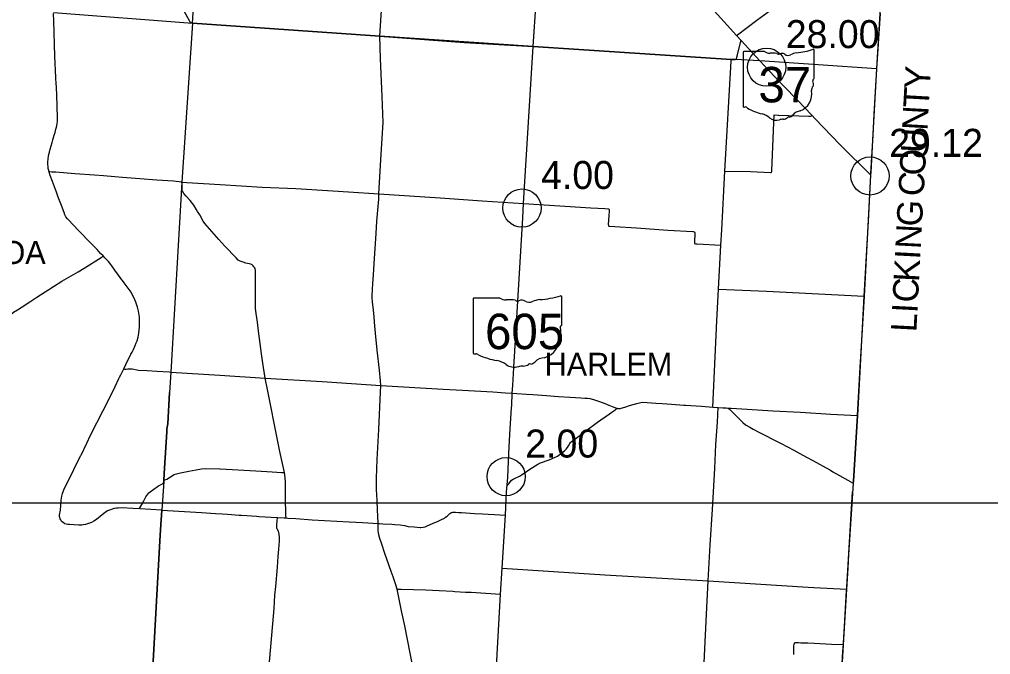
# Model space of a CAD drawing. Extents: x 1729596 to 1934326, y 644115 to 911751.
# Drawn here: x 1863218 to 1901343, y 778712 to 803658 of the extents above; entities that cross this region are included whole.
import ezdxf

# ---------------------------------------------------------------- set-up
doc = ezdxf.new("R2010")
doc.units = 0
for name, color, linetype in [('Default', 7, 'Continuous'), ('GM_X_Adjacent_County', 7, 'Continuous'), ('GM_X_Adjacent_County_Text', 7, 'Continuous'), ('GM_X_County', 7, 'Continuous'), ('GM_X_County_Road', 7, 'Continuous'), ('GM_X_State_Route', 7, 'Continuous'), ('GM_X_State_Shield', 7, 'Continuous'), ('GM_X_Township', 7, 'Continuous'), ('GM_X_Township_Road', 7, 'Continuous'), ('GM_X_Township_Text', 7, 'Continuous'), ('SC_Scratch1', 7, 'Continuous')]:
    doc.layers.add(name, color=color, linetype=linetype)

msp = doc.modelspace()

# ---------------------------------------------------------------- linework, layer by layer
at = {"layer": 'Default'}
for centre in [(1892552, 801780), (1896611, 797510), (1882946, 796248), (1882325, 785700)]:
    msp.add_circle(centre, 750, dxfattribs=at)
at = {"layer": 'GM_X_Adjacent_County'}
msp.add_line((1895282, 774451), (1895925, 785099), dxfattribs=at)
at = {"layer": 'GM_X_County'}
msp.add_lwpolyline([(1897004, 803896), (1896867, 801714), (1896762, 799856), (1896723, 799168), (1896641, 797645), (1896629, 797539), (1896376, 792790), (1896278, 791042), (1896113, 788102), (1895956, 785523), (1895947, 785445), (1895896, 784633), (1895772, 782650), (1895741, 782103), (1895686, 781278), (1895557, 779101), (1895391, 776219)], dxfattribs=at)
at = {"layer": 'GM_X_County_Road'}
for points in [[(1896877, 801685), (1896878, 801713), (1896961, 803039), (1897015, 803890), (1897038, 804349), (1897401, 810812), (1897452, 811576), (1897482, 811930), (1897540, 812982), (1897564, 813416)], [(1867396, 808359), (1867578, 807822), (1867722, 807411), (1867905, 806886), (1867988, 806661), (1868047, 806496), (1868091, 806398), (1868141, 806295), (1868218, 806162), (1868595, 805529), (1868820, 805149), (1868910, 805003), (1868961, 804924), (1869020, 804860), (1869146, 804736), (1869355, 804533), (1869481, 804376), (1869529, 804297), (1869678, 803996), (1869885, 803620), (1869914, 803562), (1869930, 803545)], [(1877369, 802994), (1877508, 805242), (1877600, 806419), (1877627, 806773)], [(1864668, 796879), (1864590, 797083), (1864513, 797287), (1864422, 797530), (1864380, 797664), (1864367, 797719), (1864351, 797802), (1864341, 797885), (1864336, 797962), (1864335, 798045), (1864343, 798179), (1864359, 798293), (1864372, 798348), (1864397, 798443), (1864431, 798566), (1864503, 798820), (1864532, 798925), (1864588, 799118), (1864615, 799218), (1864650, 799343), (1864671, 799432), (1864694, 799556), (1864707, 799664), (1864713, 799761), (1864693, 800283), (1864667, 801023), (1864657, 801114), (1864648, 801383), (1864604, 802208), (1864568, 803602), (1864561, 803891)], [(1869930, 803545), (1869936, 803538), (1870008, 803514), (1877369, 802994)], [(1877332, 796811), (1877420, 798367), (1877499, 799608), (1877454, 800633), (1877398, 802125), (1877369, 802994)], [(1896641, 797536), (1896646, 797601), (1896729, 799110), (1896778, 799931), (1896816, 800595), (1896842, 801059), (1896877, 801685)], [(1869596, 797271), (1869264, 797299), (1868606, 797350), (1867949, 797398), (1867262, 797449), (1866957, 797476), (1866512, 797510), (1866160, 797537), (1865389, 797594), (1864651, 797652), (1864490, 797665), (1864412, 797670), (1864397, 797669), (1864380, 797664)], [(1872512, 792112), (1872490, 792299), (1872490, 792441), (1872490, 792557), (1872490, 792879), (1872488, 793281), (1872492, 793732), (1872489, 793791), (1872473, 793859), (1872454, 793904), (1872424, 793943), (1872389, 793984), (1872352, 794016), (1872303, 794045), (1872239, 794060), (1872103, 794090), (1871997, 794120), (1871888, 794161), (1871806, 794204), (1871722, 794290), (1871282, 794757), (1871051, 795010), (1870503, 795638), (1870435, 795737), (1870300, 795980), (1870212, 796114), (1870156, 796211), (1870067, 796366), (1869918, 796549), (1869770, 796721), (1869677, 796824), (1869643, 796870), (1869617, 796918), (1869609, 796940), (1869604, 796966), (1869603, 796991), (1869604, 797040), (1869606, 797200), (1869596, 797271)], [(1869596, 797271), (1869794, 797255), (1871103, 797168), (1872753, 797073), (1874071, 797014), (1875527, 796924), (1876143, 796885), (1877332, 796811)], [(1896288, 791046), (1896384, 792784), (1896550, 795738), (1896641, 797536)], [(1866503, 794368), (1866405, 794466), (1866272, 794620), (1866088, 794799), (1865870, 795027), (1865711, 795195), (1865579, 795328), (1865290, 795631), (1865178, 795747), (1865101, 795824), (1865042, 795902), (1865004, 795980), (1864969, 796070), (1864868, 796347), (1864745, 796675), (1864687, 796830), (1864668, 796879)], [(1877401, 789284), (1877390, 789464), (1877348, 789877), (1877267, 790662), (1877198, 791335), (1877163, 791768), (1877144, 791994), (1877118, 792235), (1877082, 792567), (1877064, 792727), (1877062, 792815), (1877091, 793291), (1877116, 793631), (1877141, 794076), (1877219, 795256), (1877251, 795728), (1877331, 796597), (1877332, 796811)], [(1877332, 796811), (1879735, 796644), (1881379, 796538), (1883003, 796429), (1885646, 796260), (1886199, 796226), (1886342, 796212), (1886365, 796195), (1886376, 796165), (1886375, 796124), (1886362, 795947), (1886335, 795601), (1886339, 795571), (1886347, 795554), (1886359, 795544), (1886386, 795534), (1886593, 795523), (1887442, 795472), (1888679, 795387), (1889657, 795329), (1889685, 795326), (1889702, 795320), (1889718, 795310), (1889731, 795291), (1889734, 795271), (1889715, 794891), (1889718, 794875), (1889726, 794861), (1889758, 794850), (1889831, 794843), (1890758, 794790)], [(1862331, 790993), (1862331, 790993), (1862425, 791233), (1862464, 791347), (1862553, 791556), (1862621, 791712), (1862718, 791870), (1862878, 792073), (1862988, 792163), (1863137, 792257), (1863326, 792369), (1863622, 792566), (1863901, 792746), (1864887, 793380), (1865528, 793748), (1865763, 793892), (1866421, 794305), (1866453, 794326), (1866503, 794368)], [(1867241, 793436), (1867175, 793524), (1867110, 793619), (1866968, 793805), (1866845, 793974), (1866805, 794027), (1866710, 794146), (1866624, 794245), (1866569, 794300), (1866503, 794368)], [(1867153, 789604), (1867200, 789700), (1867319, 789935), (1867396, 790101), (1867504, 790327), (1867565, 790450), (1867596, 790512), (1867641, 790592), (1867690, 790690), (1867763, 790847), (1867804, 790955), (1867838, 791037), (1867877, 791180), (1867910, 791333), (1867929, 791569), (1867933, 791826), (1867927, 791967), (1867917, 792047), (1867886, 792196), (1867849, 792363), (1867813, 792478), (1867788, 792552), (1867745, 792648), (1867704, 792736), (1867647, 792848), (1867599, 792941), (1867524, 793055), (1867442, 793157), (1867330, 793312), (1867263, 793407), (1867241, 793436)], [(1872978, 777819), (1873212, 780520), (1873251, 781046), (1873282, 781384), (1873344, 782141), (1873381, 782566), (1873402, 782850), (1873426, 783163), (1873427, 783321), (1873418, 783441), (1873405, 783505), (1873393, 783554), (1873368, 783600), (1873335, 783652), (1873325, 783665), (1873319, 783693), (1873320, 783725), (1873324, 783797), (1873340, 783963), (1873351, 784093), (1873606, 784082), (1873683, 784083), (1873682, 784168), (1873669, 784889), (1873663, 785162), (1873657, 785466), (1873655, 785664), (1873627, 785869), (1873446, 786682), (1873351, 787142), (1872964, 789059), (1872863, 789571), (1872778, 790159), (1872727, 790526), (1872666, 790930), (1872604, 791411), (1872559, 791766), (1872513, 792107), (1872512, 792112)], [(1895958, 785443), (1895961, 785520), (1896121, 788099), (1896226, 789994), (1896288, 791046)], [(1865634, 786531), (1865642, 786548), (1865861, 787020), (1866012, 787331), (1866508, 788298), (1866790, 788861), (1866977, 789237), (1867126, 789549), (1867153, 789604)], [(1872863, 789571), (1875101, 789435), (1877401, 789284), (1879855, 789132), (1880616, 789098), (1881806, 789028), (1882295, 788997), (1882567, 788975)], [(1878692, 778117), (1878562, 778774), (1878349, 779845), (1878222, 780426), (1878129, 780890), (1878049, 781278), (1877993, 781449), (1877886, 781763), (1877812, 781976), (1877647, 782454), (1877568, 782686), (1877444, 783047), (1877370, 783269), (1877325, 783417), (1877310, 783511), (1877305, 783560), (1877299, 783658), (1877295, 783854), (1877283, 784157), (1877278, 784375), (1877260, 784771), (1877240, 785195), (1877237, 785645), (1877265, 786378), (1877326, 787557), (1877396, 789022), (1877401, 789284)], [(1882567, 788975), (1882741, 788963), (1883125, 788937), (1883370, 788921), (1883909, 788888), (1884378, 788846), (1884839, 788818), (1885253, 788795), (1885410, 788787), (1885513, 788777), (1885610, 788763), (1885755, 788729), (1885907, 788682), (1886172, 788583), (1886362, 788508), (1886482, 788459), (1886595, 788414), (1886653, 788392), (1886680, 788385), (1886713, 788376), (1886731, 788374), (1886750, 788372), (1886768, 788373), (1886797, 788377), (1887028, 788442), (1887172, 788488), (1887461, 788573), (1887615, 788617), (1887686, 788622), (1887858, 788617), (1888201, 788587), (1888444, 788572), (1888821, 788548), (1889303, 788508), (1889365, 788503), (1889989, 788465), (1890439, 788430), (1890646, 788418), (1890829, 788409), (1890966, 788400), (1891025, 788386), (1891044, 788379), (1891062, 788369), (1891080, 788359), (1891096, 788347), (1891113, 788333), (1891216, 788229), (1891350, 788086), (1891449, 787991), (1891616, 787833), (1891727, 787741), (1891886, 787645), (1892027, 787567), (1892268, 787440), (1892505, 787318), (1892785, 787171), (1893118, 786998), (1893620, 786737), (1893978, 786545), (1894504, 786258), (1894890, 786043), (1895054, 785951), (1895157, 785895), (1895411, 785750), (1895736, 785562), (1895925, 785459), (1895958, 785443)], [(1868439, 777975), (1868734, 783178), (1868751, 783613), (1868806, 784389), (1867942, 784436), (1867676, 784450), (1867236, 784472), (1867100, 784466), (1867030, 784459), (1866941, 784445), (1866864, 784426), (1866789, 784401), (1866682, 784352), (1866580, 784287), (1866468, 784200), (1866242, 784020), (1866138, 783951), (1866042, 783902), (1865893, 783841), (1865807, 783819), (1865720, 783803), (1865668, 783796), (1865550, 783792), (1865186, 783818), (1865114, 783826), (1865049, 783836), (1865006, 783850), (1864986, 783859), (1864948, 783880), (1864897, 783921), (1864860, 783965), (1864838, 784001), (1864822, 784040), (1864798, 784100), (1864795, 784137), (1864796, 784206), (1864829, 784383), (1864841, 784568), (1864856, 784770), (1864885, 784933), (1864914, 785038), (1864961, 785176), (1865080, 785426), (1865258, 785787), (1865446, 786179), (1865634, 786531)], [(1895289, 774451), (1895396, 776220), (1895437, 776878), (1895549, 778840), (1895565, 779105), (1895662, 780753), (1895692, 781225), (1895695, 781277), (1895727, 781798), (1895781, 782638), (1895891, 784421), (1895958, 785443)], [(1868806, 784389), (1870363, 784286), (1870916, 784253), (1871172, 784239), (1871392, 784221), (1871840, 784193), (1871932, 784185), (1872143, 784168), (1872331, 784155), (1872524, 784144), (1872620, 784137), (1873351, 784093)]]:
    msp.add_lwpolyline(points, dxfattribs=at)
at = {"layer": 'GM_X_State_Route'}
for points in [[(1883945, 807913), (1884008, 807879), (1884894, 807348), (1887358, 805901), (1889702, 804583), (1889965, 804433), (1890068, 804367), (1890146, 804309), (1890221, 804252), (1890297, 804190), (1890369, 804123), (1890999, 803432), (1891373, 803023), (1891553, 802825), (1892288, 802025), (1892862, 801410), (1894115, 800116), (1894249, 799980), (1894338, 799884), (1894447, 799772), (1895444, 798735), (1896641, 797536)], [(1882720, 791504), (1882978, 795867), (1883003, 796429), (1883088, 797714), (1883392, 802588), (1883500, 804351), (1883543, 804938), (1883588, 805754), (1883679, 807097), (1883681, 807137)], [(1882488, 787572), (1882536, 788409), (1882544, 788490), (1882567, 788975), (1882584, 789282), (1882631, 789981), (1882641, 790234), (1882655, 790407), (1882720, 791504)], [(1881788, 775208), (1881798, 775531), (1881825, 775865), (1881869, 776825), (1881921, 777694), (1881972, 778710), (1882105, 781091), (1882171, 782101), (1882295, 784185), (1882344, 785085), (1882365, 785373), (1882388, 785663), (1882412, 786305), (1882436, 786610), (1882462, 787116), (1882488, 787572)]]:
    msp.add_lwpolyline(points, dxfattribs=at)
at = {"layer": 'GM_X_State_Shield'}
for p, q in [((1891630, 802365), (1891630, 800251)), ((1891630, 802365), (1891630, 800251)), ((1892472, 802401), (1891657, 802401)), ((1892472, 802401), (1891657, 802401)), ((1894414, 801348), (1894414, 802453)), ((1894414, 801348), (1894414, 802453)), ((1894414, 801348), (1894414, 801348)), ((1894414, 801348), (1894414, 801348)), ((1881028, 792671), (1881028, 790558)), ((1881028, 792671), (1881028, 790558)), ((1882082, 792708), (1881063, 792708)), ((1882082, 792708), (1881063, 792708)), ((1884509, 791655), (1884509, 792760)), ((1884509, 791655), (1884509, 792760)), ((1884508, 791655), (1884509, 791655)), ((1884508, 791655), (1884509, 791655))]:
    msp.add_line(p, q, dxfattribs=at)
for centre, radius, start, end in [((1891661, 802369), 32.3, 98.1301, 188.1301), ((1891661, 802369), 32.3, 98.1301, 188.1301), ((1892667, 802646), 313, 231.6195, 271.1119), ((1892667, 802646), 313, 231.6195, 271.1119), ((1892770, 801215), 1123, 80.4867, 94.9883), ((1892770, 801215), 1123, 80.4867, 94.9883), ((1893025, 802380), 90.3, 219.7921, 297.1024), ((1893025, 802380), 90.3, 219.7921, 297.1024), ((1893158, 802136), 188, 54.4667, 119.1411), ((1893158, 802136), 188, 54.4667, 119.1411), ((1893400, 802471), 226, 233.8562, 294.8282), ((1893400, 802471), 226, 233.8562, 294.8282), ((1893799, 801756), 594, 97.3462, 120.7689), ((1893799, 801756), 594, 97.3462, 120.7689), ((1893422, 805282), 2953, 275.8445, 288.9065), ((1893422, 805282), 2953, 275.8445, 288.9065), ((1894383, 802458), 31, 351.8621, 97.738), ((1894383, 802458), 31, 351.8621, 97.738), ((1894525, 800885), 210, 136.8065, 186.9296), ((1894525, 800885), 210, 136.8065, 186.9296), ((1894407, 801267), 48, 107.944, 210.337), ((1894407, 801267), 48, 107.944, 210.337), ((1894102, 801127), 288, 340.033, 23.6496), ((1894102, 801127), 288, 340.033, 23.6496), ((1894381, 801344), 33.2, 289.6038, 7.7341), ((1894381, 801344), 33.2, 289.6038, 7.7341), ((1893587, 800745), 739, 292.3089, 8.9858), ((1893587, 800745), 739, 292.3089, 8.9858), ((1891662, 800247), 32.5, 171.9584, 258.3066), ((1891662, 800247), 32.5, 171.9584, 258.3066), ((1891667, 800463), 248, 267.339, 280.6039), ((1891667, 800463), 248, 267.339, 280.6039), ((1891717, 800129), 89.5, 29.7484, 93.2717), ((1891717, 800129), 89.5, 29.7484, 93.2717), ((1892848, 802028), 2132, 240.4129, 257.1985), ((1892848, 802028), 2132, 240.4129, 257.1985), ((1892212, 799302), 667, 47.1842, 75.836), ((1892212, 799302), 667, 47.1842, 75.836), ((1893386, 800047), 239, 282.8732, 323.2771), ((1893386, 800047), 239, 282.8732, 323.2771), ((1893899, 799658), 404, 94.4031, 142.5768), ((1893899, 799658), 404, 94.4031, 142.5768), ((1892934, 800119), 423, 230.7004, 286.2918), ((1892934, 800119), 423, 230.7004, 286.2918), ((1893178, 799388), 348, 85.6951, 111.2099), ((1893178, 799388), 348, 85.6951, 111.2099), ((1893209, 799961), 226, 268.777, 315.5493), ((1893209, 799961), 226, 268.777, 315.5493), ((1893413, 799756), 63.5, 65.7517, 132.6484), ((1893413, 799756), 63.5, 65.7517, 132.6484)]:
    msp.add_arc(centre, radius, start, end, dxfattribs=at)
for centre, major_axis, start_param, end_param in [((1881068, 792676), (40.3, 0), 1.712693, 3.28349), ((1881068, 792676), (40.3, 0), 1.712693, 3.28349), ((1882325, 792953), (391, 0), 4.042523, 4.731795), ((1882325, 792953), (391, 0), 4.042523, 4.731795), ((1882454, 791521), (1404, 0), 1.404758, 1.657858), ((1882454, 791521), (1404, 0), 1.404758, 1.657858), ((1882773, 792687), (113, 0), 3.836095, 5.185415), ((1882773, 792687), (113, 0), 3.836095, 5.185415), ((1882939, 792443), (235, 0), 0.950623, 2.079405), ((1882939, 792443), (235, 0), 0.950623, 2.079405), ((1883740, 792062), (743, 0), 1.699011, 2.107814), ((1883740, 792062), (743, 0), 1.699011, 2.107814), ((1883269, 795589), (3691, 0), 4.814394, 5.042369), ((1883269, 795589), (3691, 0), 4.814394, 5.042369), ((1884470, 792765), (38.7, 0), 6.141152, 7.989035), ((1884470, 792765), (38.7, 0), 6.141152, 7.989035), ((1883241, 792778), (282, 0), 4.081561, 5.145723), ((1883241, 792778), (282, 0), 4.081561, 5.145723), ((1884500, 791574), (60, 0), 1.883978, 3.671073), ((1884500, 791574), (60, 0), 1.883978, 3.671073), ((1884118, 791434), (360, 0), 5.934695, 6.695948), ((1884118, 791434), (360, 0), 5.934695, 6.695948), ((1884468, 791650), (41.5, 0), 5.05454, 6.418171), ((1884468, 791650), (41.5, 0), 5.05454, 6.418171), ((1883476, 791051), (923, 0), 5.101752, 6.440018), ((1883476, 791051), (923, 0), 5.101752, 6.440018), ((1884648, 791192), (262, 0), 2.387724, 3.262537), ((1884648, 791192), (262, 0), 2.387724, 3.262537), ((1881069, 790554), (40.7, 0), 3.00124, 4.508301), ((1881069, 790554), (40.7, 0), 3.00124, 4.508301), ((1881075, 790770), (310, 0), 4.665946, 4.897461), ((1881075, 790770), (310, 0), 4.665946, 4.897461), ((1881138, 790436), (112, 0), 0.519207, 1.627899), ((1881138, 790436), (112, 0), 0.519207, 1.627899), ((1882552, 792335), (2665, 0), 4.195997, 4.488961), ((1882552, 792335), (2665, 0), 4.195997, 4.488961), ((1883865, 789965), (506, 0), 1.647645, 2.488434), ((1883865, 789965), (506, 0), 1.647645, 2.488434), ((1881757, 789609), (834, 0), 0.823519, 1.323587), ((1881757, 789609), (834, 0), 0.823519, 1.323587), ((1882659, 790426), (529, 0), 4.026481, 4.996735), ((1882659, 790426), (529, 0), 4.026481, 4.996735), ((1882965, 789695), (435, 0), 1.495662, 1.94098), ((1882965, 789695), (435, 0), 1.495662, 1.94098), ((1883003, 790268), (282, 0), 4.691044, 5.507374), ((1883003, 790268), (282, 0), 4.691044, 5.507374), ((1883258, 790063), (79.4, 0), 1.147584, 2.315152), ((1883258, 790063), (79.4, 0), 1.147584, 2.315152), ((1883224, 790353), (298, 0), 4.937069, 5.64225), ((1883224, 790353), (298, 0), 4.937069, 5.64225)]:
    msp.add_ellipse(centre, major_axis=major_axis, ratio=0.8, start_param=start_param, end_param=end_param, dxfattribs=at)
at = {"layer": 'GM_X_Township'}
for points in [[(1896867, 801714), (1892288, 802025), (1891297, 802083), (1891221, 802088), (1891165, 802089), (1883392, 802588), (1877369, 802994), (1870008, 803514), (1870309, 808163)], [(1864561, 803926), (1870008, 803514), (1869596, 797271), (1869163, 789806), (1869111, 789007), (1869039, 787768), (1869000, 787580), (1869008, 787459), (1868914, 786029), (1868892, 785569), (1868890, 785515), (1868806, 784389), (1868751, 783613), (1868734, 783178), (1868439, 777975), (1868321, 776001)]]:
    msp.add_lwpolyline(points, dxfattribs=at)
at = {"layer": 'GM_X_Township_Road'}
for points in [[(1891373, 803023), (1891387, 803039), (1891405, 803057), (1892171, 803626), (1892889, 804151), (1893142, 808538), (1893444, 812998), (1893450, 813114), (1893446, 813209)], [(1877369, 802994), (1880691, 802757), (1883392, 802588)], [(1883392, 802588), (1891165, 802089)], [(1891312, 802088), (1891337, 802094), (1891347, 802102), (1891354, 802110), (1891365, 802128), (1891402, 802264), (1891525, 802755), (1891537, 802794), (1891544, 802811), (1891553, 802825)], [(1890439, 788430), (1890599, 791825), (1890663, 793067), (1890758, 794790), (1890789, 795400), (1890905, 797697), (1891157, 802023), (1891165, 802089), (1891207, 802088)], [(1891207, 802088), (1891221, 802088), (1891297, 802083), (1891312, 802088)], [(1890905, 797697), (1891923, 797682), (1892705, 797649), (1892735, 797650), (1892749, 797657), (1892754, 797681), (1892755, 797718), (1892849, 799904), (1892999, 799898)], [(1892999, 799898), (1893021, 799897), (1894207, 799861), (1894280, 799859), (1894312, 799865), (1894338, 799884)], [(1890663, 793067), (1892550, 792979), (1896384, 792784)], [(1867319, 789935), (1867341, 789922), (1867365, 789918), (1867384, 789918), (1867408, 789922), (1867479, 789935), (1867531, 789940), (1867600, 789940), (1867638, 789937), (1867706, 789923), (1867821, 789895), (1867896, 789887), (1868229, 789864), (1868613, 789842), (1869090, 789811)], [(1869090, 789811), (1869163, 789806), (1871085, 789686), (1872863, 789571)], [(1868892, 785569), (1868914, 786029), (1869008, 787459), (1869000, 787580), (1869039, 787768), (1869111, 789007)], [(1882683, 785641), (1882855, 785721), (1882997, 785815), (1883257, 785993), (1883565, 786185), (1883679, 786242), (1884012, 786364), (1884230, 786446), (1884346, 786511), (1884516, 786635), (1884621, 786715), (1884686, 786778), (1884731, 786841), (1884769, 786909), (1884825, 787001), (1884855, 787037), (1884882, 787064), (1885068, 787213), (1885458, 787501), (1885907, 787835), (1886041, 787935), (1886384, 788169), (1886469, 788228), (1886553, 788290), (1886680, 788385)], [(1889887, 774731), (1890002, 776489), (1890176, 780026), (1890259, 781603), (1890338, 783022), (1890423, 784415), (1890516, 786023), (1890561, 786967), (1890617, 787839), (1890646, 788418)], [(1890966, 788400), (1891033, 788396), (1891153, 788392), (1891791, 788356), (1892800, 788289), (1893883, 788232), (1895073, 788154), (1896121, 788099)], [(1868902, 785570), (1868932, 785574), (1869001, 785603), (1869292, 785779), (1869311, 785786)], [(1869311, 785786), (1869335, 785796), (1869538, 785844), (1869873, 785912), (1870158, 785969), (1870363, 786009), (1870524, 786025), (1871080, 786004), (1871097, 786003)], [(1871097, 786003), (1872502, 785926), (1873145, 785890), (1873503, 785869), (1873627, 785869)], [(1867942, 784436), (1867949, 784478), (1868023, 784612), (1868101, 784749), (1868183, 784905), (1868256, 785017), (1868303, 785069), (1868353, 785099), (1868641, 785317), (1868679, 785339), (1868830, 785413), (1868860, 785439), (1868876, 785462), (1868890, 785515), (1868891, 785527)], [(1868891, 785527), (1868892, 785569), (1868902, 785570)], [(1882365, 785373), (1882398, 785385), (1882433, 785419), (1882534, 785556), (1882606, 785605), (1882683, 785641)], [(1878710, 783724), (1878718, 783723), (1878952, 783700), (1878974, 783698), (1879074, 783716), (1879141, 783735), (1879196, 783761), (1879454, 783879), (1879626, 783945), (1879759, 784003), (1879901, 784076), (1879948, 784106), (1880010, 784152), (1880078, 784216), (1880118, 784255), (1880153, 784278), (1880179, 784290), (1880195, 784296), (1880230, 784302), (1880247, 784303), (1880334, 784300), (1880449, 784295), (1880574, 784290), (1881079, 784258), (1881400, 784242), (1881619, 784230), (1881872, 784212), (1882079, 784200), (1882295, 784185)], [(1873683, 784083), (1873753, 784073), (1874065, 784055), (1874709, 784010), (1876165, 783928), (1876686, 783898), (1877295, 783854)], [(1877295, 783854), (1877356, 783857), (1877485, 783848), (1877833, 783829), (1877952, 783822), (1878166, 783809), (1878334, 783779), (1878476, 783745), (1878710, 783724)], [(1882171, 782101), (1886206, 781843), (1890259, 781603)], [(1890259, 781603), (1890259, 781603), (1894179, 781364)], [(1878049, 781278), (1878201, 781278), (1879179, 781250), (1879698, 781229), (1880226, 781199), (1880311, 781191), (1880734, 781168), (1880958, 781163), (1882105, 781091)], [(1894179, 781364), (1894411, 781350), (1895695, 781277)], [(1893617, 778714), (1893624, 779045), (1893632, 779127), (1893640, 779161), (1893657, 779180), (1893679, 779187), (1893716, 779191), (1893800, 779184), (1893892, 779175), (1894041, 779168), (1894167, 779168), (1894412, 779159), (1895102, 779119), (1895565, 779105)]]:
    msp.add_lwpolyline(points, dxfattribs=at)
at = {"layer": 'SC_Scratch1'}
msp.add_lwpolyline([(1730291, 784675), (1926541, 784675), (1926541, 650175), (1730291, 650175)], close=True, dxfattribs=at)

# ---------------------------------------------------------------- texts
at = {"layer": 'Default'}
for s, p in [('28.00', (1893302, 802530)), ('29.12', (1897361, 798260)), ('4.00', (1883696, 796998)), ('2.00', (1883075, 786450))]:
    msp.add_text(s, height=1100, dxfattribs=at).set_placement(p)
at = {"layer": 'GM_X_Adjacent_County_Text'}
for s, rotation, p in [('Y', 86.7665, (1898954, 800905)), ('T', 86.7674, (1898911, 800158)), ('N', 86.7675, (1898862, 799275)), ('U', 86.7602, (1898812, 798392)), ('O', 86.7321, (1898761, 797508)), ('C', 86.4487, (1898710, 796690)), ('G', 86.9419, (1898647, 795506)), ('N', 86.9747, (1898600, 794623)), ('K', 86.9789, (1898532, 793332)), ('I', 86.9739, (1898579, 794215)), ('C', 86.98, (1898489, 792519)), ('I', 86.9808, (1898468, 792110)), ('L', 86.9798, (1898428, 791363))]:
    msp.add_text(s, height=1000, rotation=rotation, dxfattribs=at).set_placement(p)
at = {"layer": 'GM_X_State_Shield'}
for s, p in [('37', (1892230, 800400)), ('37', (1892230, 800400)), ('605', (1881497, 790707)), ('605', (1881497, 790707))]:
    msp.add_text(s, height=1392.2, dxfattribs=at).set_placement(p)
at = {"layer": 'GM_X_Township_Text'}
for s, p in [('GENOA', (1859903, 794055)), ('HARLEM', (1883833, 789665))]:
    msp.add_text(s, height=900, rotation=0, dxfattribs=at).set_placement(p)

doc.saveas('drawing.dxf')
